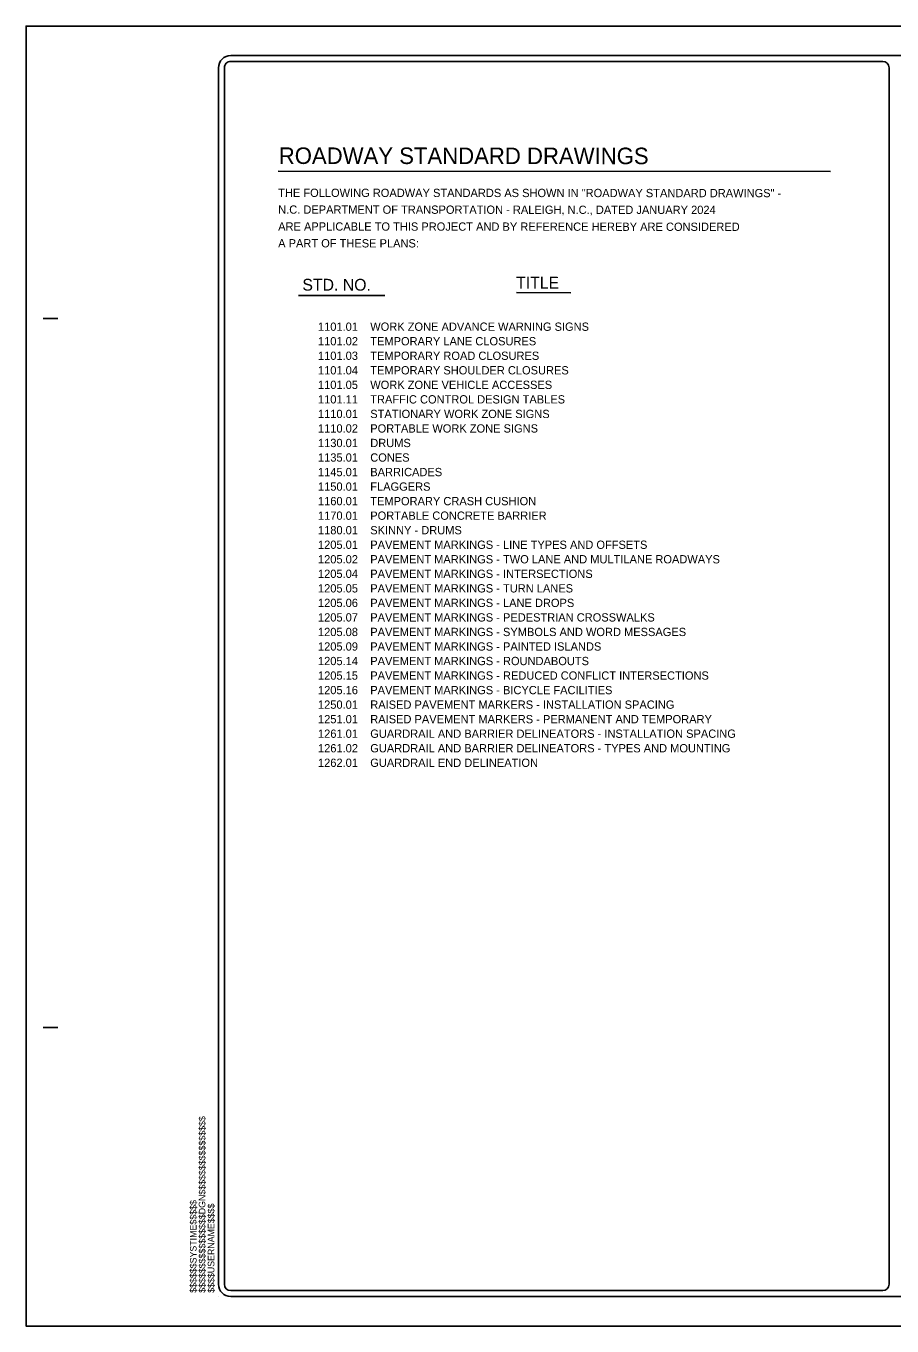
# Model space of a CAD drawing. Extents: x 1403867 to 1405555, y 486423 to 487523.
# Drawn here: x 1403867 to 1404600, y 486423 to 487523 of the extents above; entities that cross this region are included whole.
import ezdxf

# ---------------------------------------------------------------- set-up
doc = ezdxf.new("R2010")
doc.units = 0
doc.layers.add('DEV BORDER CELL', color=7, linetype='Continuous')
doc.layers.add('Sheet Plot Border Outside CELL', color=7, linetype='Continuous')

msp = doc.modelspace()

# ---------------------------------------------------------------- linework, layer by layer
at = {"layer": 'DEV BORDER CELL'}
for p, q in [((1404030.4, 487487.4), (1404030.4, 486458)), ((1404035.4, 487487.4), (1404035.4, 486458)), ((1405520.1, 487497.7), (1404040.6, 487497.7)), ((1404592.6, 487492.7), (1404040.6, 487492.7)), ((1404597.8, 487487.4), (1404597.8, 486458)), ((1404080.7, 487399.9), (1404548.4, 487399.6)), ((1404097.9, 487294.7), (1404171.2, 487294.7)), ((1404111.9, 487294.7), (1404111.9, 487294.7)), ((1404111.9, 487294.7), (1404111.9, 487294.7)), ((1404282.4, 487297.1), (1404328.4, 487297)), ((1403881.9, 487275.2), (1403894.4, 487275.2)), ((1403881.9, 486675.2), (1403894.4, 486675.2)), ((1404030.4, 486447.7), (1404030.4, 486447.7)), ((1404040.6, 486452.7), (1404592.6, 486452.7)), ((1404040.6, 486447.7), (1405520.1, 486447.7))]:
    msp.add_line(p, q, dxfattribs=at)
for centre, radius, start, end in [((1404040.6, 487487.4), 10.3, 89.9972, 180), ((1404040.6, 487487.4), 5.29, 89.9972, 180), ((1404592.6, 487487.4), 5.29, 0.0001, 89.9995), ((1404040.6, 486458), 10.3, 180, 270), ((1404040.6, 486458), 5.29, 180, 270), ((1404592.6, 486458), 5.29, 270.0005, 359.9999)]:
    msp.add_arc(centre, radius, start, end, dxfattribs=at)
at = {"layer": 'Sheet Plot Border Outside CELL'}
for points in [[(1403867.4, 486422.7), (1403867.4, 487522.7), (1405555.4, 487522.7), (1405555.4, 486422.7)], [(1403867.4, 487522.7), (1405555.4, 487522.7), (1405555.4, 486422.7), (1403867.4, 486422.7)], [(1403867.4, 486422.7), (1405555.4, 486422.7), (1405555.4, 487522.7), (1403867.4, 487522.7)]]:
    msp.add_lwpolyline(points, close=True, dxfattribs=at)

# ---------------------------------------------------------------- texts
at = {"layer": 'DEV BORDER CELL'}
for s, height, rotation, p in [('ROADWAY STANDARD DRAWINGS', 13.999, 359.9598, (1404081.3, 487406)), ('THE FOLLOWING ROADWAY STANDARDS AS SHOWN IN "ROADWAY STANDARD DRAWINGS" -', 7, 359.9598, (1404080.8, 487378.1)), ('N.C. DEPARTMENT OF TRANSPORTATION - RALEIGH, N.C., DATED JANUARY 2024', 7, 359.9598, (1404080.8, 487363.9)), ('ARE APPLICABLE TO THIS PROJECT AND BY REFERENCE HEREBY ARE CONSIDERED', 7, 359.9598, (1404080.8, 487349.6)), ('A PART OF THESE PLANS:', 7, 359.9598, (1404080.8, 487335.4)), ('STD. NO.', 10, 359.9598, (1404101.3, 487298.8)), ('TITLE', 10, 359.9598, (1404282.2, 487300.5)), ('$$$$$$$$$$$$$$$$DGN$$$$$$$$$$$$$$$$', 5.584, 90, (1404019.2, 486450.8)), ('$$$$$$SYSTIME$$$$$', 5.584, 90, (1404011.7, 486450.8)), ('$$$$USERNAME$$$$', 5.584, 90, (1404026.8, 486450.8))]:
    msp.add_text(s, height=height, rotation=rotation, dxfattribs=at).set_placement(p)
for s, p in [('1101.01    WORK ZONE ADVANCE WARNING SIGNS', (1404114.5, 487264.8)), ('1101.02    TEMPORARY LANE CLOSURES', (1404114.5, 487252.5)), ('1101.03    TEMPORARY ROAD CLOSURES', (1404114.5, 487240.2)), ('1101.04    TEMPORARY SHOULDER CLOSURES', (1404114.5, 487227.9)), ('1101.05    WORK ZONE VEHICLE ACCESSES', (1404114.5, 487215.6)), ('1101.11    TRAFFIC CONTROL DESIGN TABLES', (1404114.5, 487203.3)), ('1110.01    STATIONARY WORK ZONE SIGNS', (1404114.5, 487191)), ('1110.02    PORTABLE WORK ZONE SIGNS', (1404114.5, 487178.7)), ('1130.01    DRUMS ', (1404114.5, 487166.4)), ('1135.01    CONES', (1404114.5, 487154.1)), ('1145.01    BARRICADES', (1404114.5, 487141.8)), ('1150.01    FLAGGERS', (1404114.5, 487129.5)), ('1160.01    TEMPORARY CRASH CUSHION ', (1404114.5, 487117.2)), ('1170.01    PORTABLE CONCRETE BARRIER ', (1404114.5, 487104.9)), ('1180.01    SKINNY - DRUMS', (1404114.5, 487092.6)), ('1205.01    PAVEMENT MARKINGS - LINE TYPES AND OFFSETS', (1404114.5, 487080.3)), ('1205.02    PAVEMENT MARKINGS - TWO LANE AND MULTILANE ROADWAYS', (1404114.5, 487068)), ('1205.04    PAVEMENT MARKINGS - INTERSECTIONS', (1404114.5, 487055.7)), ('1205.05    PAVEMENT MARKINGS - TURN LANES', (1404114.5, 487043.4)), ('1205.06    PAVEMENT MARKINGS - LANE DROPS', (1404114.5, 487031.1)), ('1205.07    PAVEMENT MARKINGS - PEDESTRIAN CROSSWALKS', (1404114.5, 487018.8)), ('1205.08    PAVEMENT MARKINGS - SYMBOLS AND WORD MESSAGES', (1404114.5, 487006.5)), ('1205.09    PAVEMENT MARKINGS - PAINTED ISLANDS', (1404114.5, 486994.2)), ('1205.14    PAVEMENT MARKINGS - ROUNDABOUTS', (1404114.5, 486981.9)), ('1205.15    PAVEMENT MARKINGS - REDUCED CONFLICT INTERSECTIONS', (1404114.5, 486969.6)), ('1205.16    PAVEMENT MARKINGS - BICYCLE FACILITIES', (1404114.5, 486957.3)), ('1250.01    RAISED PAVEMENT MARKERS - INSTALLATION SPACING', (1404114.5, 486945)), ('1251.01    RAISED PAVEMENT MARKERS - PERMANENT AND TEMPORARY ', (1404114.5, 486932.7)), ('1261.01    GUARDRAIL AND BARRIER DELINEATORS - INSTALLATION SPACING', (1404114.5, 486920.4)), ('1261.02    GUARDRAIL AND BARRIER DELINEATORS - TYPES AND MOUNTING ', (1404114.5, 486908.1)), ('1262.01    GUARDRAIL END DELINEATION', (1404114.5, 486895.8))]:
    msp.add_text(s, height=7, dxfattribs=at).set_placement(p)

doc.saveas('drawing.dxf')
